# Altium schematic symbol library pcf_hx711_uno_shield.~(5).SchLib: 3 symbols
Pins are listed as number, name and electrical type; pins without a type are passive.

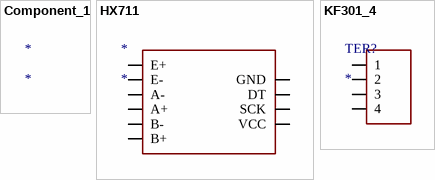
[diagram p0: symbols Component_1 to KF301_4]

## Component_1
designator *

## HX711
designator *
footprint HX711
pins: 1 E+, 2 E-, 3 A-, 4 A+, 5 B-, 6 B+, 7 GND, 8 DT, 9 SCK, 10 VCC

## KF301_4
designator TER?
footprint KF304_4
pins: 1, 2, 3, 4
